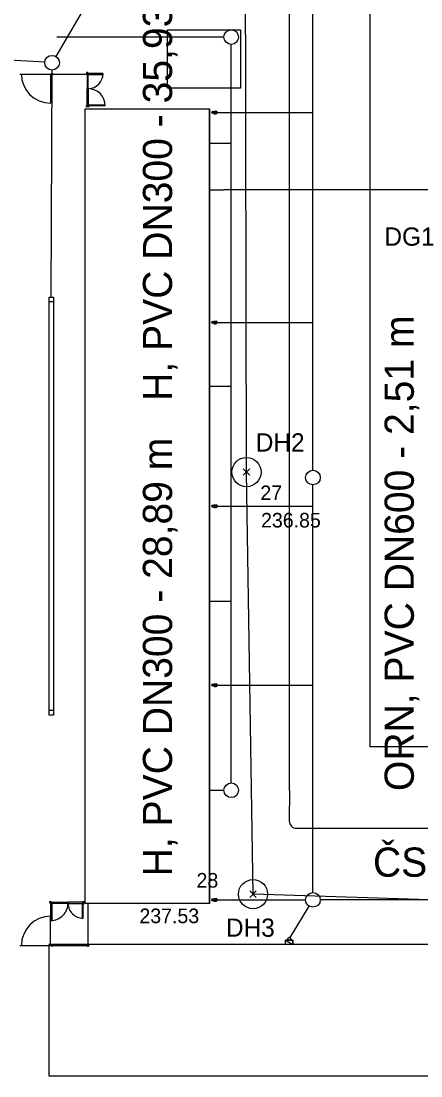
# Model space of a CAD drawing. Extents: x -264234 to -263604, y -1242346 to -1242049.
# Drawn here: x -263972 to -263944.6, y -1242264 to -1242191.8 of the extents above; entities that cross this region are included whole.
import ezdxf

# ---------------------------------------------------------------- set-up
doc = ezdxf.new("R2010")
doc.units = 0
for name, color, linetype in [('KFA_BODY_CISLO', 7, 'Continuous'), ('KFA_BODY_SYMBOL', 7, 'Continuous'), ('KFA_BODY_VYSKA', 7, 'Continuous'), ('KFA_DAZDOVA_KANALIZACIA_retencna_nadrz', 7, 'Continuous'), ('KFA_DAZDOVA_KANALIZACIA_retencna_nadrz_popis', 7, 'Continuous'), ('KFA_DAZDOVA_KANALIZACIA_vetva_G_popis', 7, 'Continuous'), ('KFA_DAZDOVA_KANALIZACIA_vetva_H', 7, 'Continuous'), ('KFA_DAZDOVA_KANALIZACIA_vetva_H_popis', 7, 'Continuous'), ('KFA_JESTV_IS_DSP_-_KANAL_DAZD', 7, 'Continuous'), ('KFA_SITUACIA_DSP', 7, 'Continuous')]:
    doc.layers.add(name, color=color, linetype=linetype)

msp = doc.modelspace()

# ---------------------------------------------------------------- linework, layer by layer
at = {"layer": 'KFA_BODY_SYMBOL'}
for p, q in [((-263956.774, -1242222.873), (-263956.332, -1242222.431)), ((-263956.332, -1242222.873), (-263956.774, -1242222.431)), ((-263956.325, -1242251.762), (-263955.883, -1242251.32)), ((-263955.883, -1242251.762), (-263956.325, -1242251.32))]:
    msp.add_line(p, q, dxfattribs=at)
at = {"layer": 'KFA_DAZDOVA_KANALIZACIA_retencna_nadrz'}
msp.add_lwpolyline([(-263941.017, -1242252.038), (-263942.63, -1242251.985), (-263956.104, -1242251.541)], dxfattribs=at)
at = {"layer": 'KFA_DAZDOVA_KANALIZACIA_vetva_H'}
msp.add_lwpolyline([(-263956.104, -1242251.541), (-263956.553, -1242222.652), (-263956.616, -1242186.719), (-263963.661, -1242184.028)], dxfattribs=at)
for centre in [(-263956.553, -1242222.652), (-263956.104, -1242251.541)]:
    msp.add_circle(centre, 1, dxfattribs=at)
at = {"layer": 'KFA_JESTV_IS_DSP_-_KANAL_DAZD'}
for p, q in [((-263963.914, -1242184.46), (-263969.615, -1242194.201)), ((-263970.367, -1242194.605), (-264044.102, -1242190.483))]:
    msp.add_line(p, q, dxfattribs=at)
msp.add_circle((-263969.868, -1242194.633), 0.5, dxfattribs=at)
at = {"layer": 'KFA_SITUACIA_DSP'}
for p, q in [((-263948.093, -1242087.901), (-263948.093, -1242241.458)), ((-263953.617, -1242244.458), (-263953.617, -1242093.307)), ((-263952, -1242222.527), (-263952, -1242182)), ((-263958.097, -1242192.883), (-263969.542, -1242192.883)), ((-263957.597, -1242243.932), (-263957.597, -1242193.383)), ((-263969.921, -1242210.683), (-263969.869, -1242195.133)), ((-263972.068, -1242195.407), (-263967.418, -1242195.407)), ((-263969.968, -1242195.407), (-263969.968, -1242197.407)), ((-263967.413, -1242195.307), (-263967.513, -1242195.307)), ((-263967.513, -1242195.307), (-263967.513, -1242195.407)), ((-263967.513, -1242195.407), (-263967.413, -1242195.407)), ((-263967.425, -1242195.32), (-263967.5, -1242195.32)), ((-263967.5, -1242195.32), (-263967.5, -1242195.395)), ((-263967.5, -1242195.395), (-263967.425, -1242195.395)), ((-263967.463, -1242195.407), (-263967.463, -1242196.395)), ((-263967.388, -1242195.407), (-263967.463, -1242195.407)), ((-263967.425, -1242195.395), (-263967.425, -1242195.32)), ((-263967.425, -1242195.395), (-263967.425, -1242195.345)), ((-263967.425, -1242195.345), (-263967.325, -1242195.345)), ((-263967.413, -1242195.407), (-263967.413, -1242195.307)), ((-263967.413, -1242195.357), (-263967.363, -1242195.357)), ((-263967.388, -1242196.395), (-263967.388, -1242195.407)), ((-263967.363, -1242195.457), (-263967.388, -1242195.457)), ((-263966.388, -1242195.371), (-263967.375, -1242195.37)), ((-263967.375, -1242195.37), (-263967.375, -1242195.445)), ((-263967.375, -1242195.445), (-263966.388, -1242195.446)), ((-263967.363, -1242195.357), (-263967.363, -1242195.457)), ((-263967.325, -1242195.345), (-263967.325, -1242195.37)), ((-263967.463, -1242197.557), (-263967.463, -1242196.42)), ((-263967.388, -1242196.42), (-263967.388, -1242197.557)), ((-263967.593, -1242252.182), (-263967.593, -1242197.782)), ((-263967.593, -1242197.782), (-263959.093, -1242197.782)), ((-263967.593, -1242197.782), (-263959.097, -1242197.782)), ((-263967.593, -1242252.182), (-263967.593, -1242197.782)), ((-263967.513, -1242197.557), (-263967.413, -1242197.557)), ((-263967.513, -1242197.657), (-263967.513, -1242197.557)), ((-263967.413, -1242197.657), (-263967.513, -1242197.657)), ((-263967.5, -1242197.57), (-263967.425, -1242197.57)), ((-263967.5, -1242197.645), (-263967.5, -1242197.57)), ((-263967.425, -1242197.645), (-263967.5, -1242197.645)), ((-263967.478, -1242197.782), (-263967.358, -1242197.782)), ((-263967.388, -1242197.557), (-263967.463, -1242197.557)), ((-263967.425, -1242197.57), (-263967.425, -1242197.62)), ((-263967.425, -1242197.57), (-263967.425, -1242197.645)), ((-263967.425, -1242197.62), (-263967.325, -1242197.62)), ((-263967.413, -1242197.557), (-263967.413, -1242197.657)), ((-263967.413, -1242197.607), (-263967.363, -1242197.607)), ((-263967.363, -1242197.507), (-263967.388, -1242197.507)), ((-263967.375, -1242197.52), (-263966.238, -1242197.52)), ((-263967.375, -1242197.595), (-263967.375, -1242197.52)), ((-263966.238, -1242197.595), (-263967.375, -1242197.595)), ((-263967.363, -1242197.607), (-263967.363, -1242197.507)), ((-263967.325, -1242197.62), (-263967.325, -1242197.595)), ((-263959.097, -1242197.782), (-263959.093, -1242252.182)), ((-263959.093, -1242197.782), (-263959.093, -1242252.182)), ((-263958.799, -1242197.962), (-263958.762, -1242197.962)), ((-263958.799, -1242198.102), (-263958.762, -1242198.102)), ((-263958.762, -1242197.962), (-263958.742, -1242197.942)), ((-263958.762, -1242198.102), (-263958.742, -1242198.122)), ((-263958.742, -1242197.942), (-263958.637, -1242197.942)), ((-263958.742, -1242198.122), (-263958.637, -1242198.122)), ((-263958.575, -1242198.032), (-263952, -1242198.032)), ((-263959.097, -1242200.132), (-263957.597, -1242200.132)), ((-263959.097, -1242203.332), (-263958.097, -1242203.332)), ((-263924.893, -1242203.332), (-263958.097, -1242203.332)), ((-263970.071, -1242210.684), (-263969.77, -1242210.682)), ((-263970.07, -1242239.282), (-263970.071, -1242210.684)), ((-263970.071, -1242210.983), (-263969.771, -1242210.985)), ((-263969.77, -1242210.682), (-263969.77, -1242239.282)), ((-263958.799, -1242212.337), (-263958.762, -1242212.337)), ((-263958.799, -1242212.477), (-263958.762, -1242212.477)), ((-263958.762, -1242212.337), (-263958.742, -1242212.317)), ((-263958.762, -1242212.477), (-263958.742, -1242212.497)), ((-263958.742, -1242212.317), (-263958.637, -1242212.317)), ((-263958.742, -1242212.497), (-263958.637, -1242212.497)), ((-263958.575, -1242212.407), (-263952, -1242212.407)), ((-263959.097, -1242216.782), (-263957.597, -1242216.782)), ((-263952, -1242251.432), (-263952, -1242223.527)), ((-263958.799, -1242224.912), (-263958.762, -1242224.912)), ((-263958.799, -1242225.052), (-263958.762, -1242225.052)), ((-263958.762, -1242224.912), (-263958.742, -1242224.892)), ((-263958.762, -1242225.052), (-263958.742, -1242225.072)), ((-263958.742, -1242224.892), (-263958.637, -1242224.892)), ((-263958.742, -1242225.072), (-263958.637, -1242225.072)), ((-263958.575, -1242224.982), (-263952, -1242224.982)), ((-263959.097, -1242231.482), (-263957.597, -1242231.482)), ((-263958.799, -1242237.162), (-263958.762, -1242237.162)), ((-263958.799, -1242237.302), (-263958.762, -1242237.302)), ((-263958.762, -1242237.162), (-263958.742, -1242237.142)), ((-263958.762, -1242237.302), (-263958.742, -1242237.322)), ((-263958.742, -1242237.142), (-263958.637, -1242237.142)), ((-263958.742, -1242237.322), (-263958.637, -1242237.322)), ((-263958.575, -1242237.232), (-263952, -1242237.232)), ((-263969.77, -1242238.982), (-263970.07, -1242238.982)), ((-263969.77, -1242239.282), (-263970.07, -1242239.282)), ((-263930.081, -1242241.458), (-263948.093, -1242241.458)), ((-263959.097, -1242244.432), (-263958.097, -1242244.432)), ((-263953.617, -1242244.458), (-263953.619, -1242246.529)), ((-263953.119, -1242247.03), (-263930.082, -1242247.03)), ((-263970.018, -1242252.152), (-263970.018, -1242252.052)), ((-263970.018, -1242252.052), (-263969.918, -1242252.052)), ((-263969.918, -1242252.152), (-263970.018, -1242252.152)), ((-263970.005, -1242252.14), (-263970.005, -1242252.065)), ((-263970.005, -1242252.065), (-263969.93, -1242252.065)), ((-263969.93, -1242252.14), (-263970.005, -1242252.14)), ((-263969.93, -1242252.14), (-263969.98, -1242252.14)), ((-263969.98, -1242252.14), (-263969.98, -1242252.24)), ((-263969.98, -1242252.24), (-263969.955, -1242252.24)), ((-263969.968, -1242252.152), (-263969.968, -1242252.202)), ((-263969.968, -1242252.202), (-263969.868, -1242252.202)), ((-263969.955, -1242253.327), (-263969.955, -1242252.19)), ((-263969.955, -1242252.19), (-263969.88, -1242252.19)), ((-263969.93, -1242252.065), (-263969.93, -1242252.14)), ((-263969.918, -1242252.052), (-263969.918, -1242252.152)), ((-263969.918, -1242252.102), (-263968.78, -1242252.102)), ((-263969.918, -1242252.177), (-263969.918, -1242252.102)), ((-263968.78, -1242252.177), (-263969.918, -1242252.177)), ((-263969.88, -1242252.19), (-263969.88, -1242253.327)), ((-263969.868, -1242252.202), (-263969.868, -1242252.177)), ((-263968.78, -1242252.102), (-263968.78, -1242252.177)), ((-263967.768, -1242252.102), (-263968.755, -1242252.102)), ((-263968.755, -1242252.102), (-263968.755, -1242252.177)), ((-263968.755, -1242252.177), (-263967.768, -1242252.177)), ((-263967.818, -1242252.202), (-263967.818, -1242252.177)), ((-263967.718, -1242252.202), (-263967.818, -1242252.202)), ((-263967.805, -1242252.19), (-263967.807, -1242253.177)), ((-263967.73, -1242252.19), (-263967.805, -1242252.19)), ((-263967.768, -1242252.152), (-263967.768, -1242252.052)), ((-263967.768, -1242252.052), (-263967.668, -1242252.052)), ((-263967.768, -1242252.177), (-263967.768, -1242252.102)), ((-263967.668, -1242252.152), (-263967.768, -1242252.152)), ((-263967.755, -1242252.14), (-263967.755, -1242252.065)), ((-263967.755, -1242252.065), (-263967.68, -1242252.065)), ((-263967.755, -1242252.14), (-263967.705, -1242252.14)), ((-263967.68, -1242252.14), (-263967.755, -1242252.14)), ((-263967.732, -1242253.177), (-263967.73, -1242252.19)), ((-263967.705, -1242252.24), (-263967.73, -1242252.24)), ((-263967.718, -1242252.152), (-263967.718, -1242252.202)), ((-263967.705, -1242252.14), (-263967.705, -1242252.24)), ((-263967.68, -1242252.065), (-263967.68, -1242252.14)), ((-263967.668, -1242252.052), (-263967.668, -1242252.152)), ((-263959.093, -1242252.182), (-263967.593, -1242252.182)), ((-263959.093, -1242252.182), (-263967.593, -1242252.182)), ((-263967.418, -1242252.182), (-263967.418, -1242255.057)), ((-263958.799, -1242251.862), (-263958.762, -1242251.862)), ((-263958.799, -1242252.002), (-263958.762, -1242252.002)), ((-263958.762, -1242251.862), (-263958.742, -1242251.842)), ((-263958.762, -1242252.002), (-263958.742, -1242252.022)), ((-263958.742, -1242251.842), (-263958.637, -1242251.842)), ((-263958.742, -1242252.022), (-263958.637, -1242252.022)), ((-263958.575, -1242251.932), (-263952.5, -1242251.932)), ((-263940.302, -1242251.932), (-263951.5, -1242251.932)), ((-263953.57, -1242254.506), (-263952.26, -1242252.359)), ((-263969.968, -1242255.057), (-263969.968, -1242253.057)), ((-263972.068, -1242255.057), (-263967.418, -1242255.057)), ((-263969.928, -1242255.057), (-263969.808, -1242255.057)), ((-263969.868, -1242255.117), (-263969.868, -1242254.997)), ((-263967.478, -1242255.057), (-263967.358, -1242255.057)), ((-263967.418, -1242255.117), (-263967.418, -1242254.997)), ((-263953.87, -1242254.692), (-263953.37, -1242254.692)), ((-263953.87, -1242254.982), (-263953.87, -1242254.692)), ((-263953.87, -1242254.692), (-263953.37, -1242254.982)), ((-263953.87, -1242254.692), (-263953.37, -1242254.982)), ((-263953.37, -1242254.692), (-263953.87, -1242254.692)), ((-263953.37, -1242254.982), (-263953.87, -1242254.982)), ((-263953.37, -1242254.692), (-263953.37, -1242254.982)), ((-263953.37, -1242254.982), (-263953.37, -1242254.692))]:
    msp.add_line(p, q, dxfattribs=at)
for points in [[(-263961.968, -1242192.382), (-263956.968, -1242192.382), (-263956.968, -1242196.382), (-263961.968, -1242196.382)], [(-263967.597, -1242197.782), (-263959.097, -1242197.782), (-263959.097, -1242252.182), (-263967.597, -1242252.182)]]:
    msp.add_lwpolyline(points, close=True, dxfattribs=at)
msp.add_lwpolyline([(-263929.58, -1242254.982), (-263970.077, -1242254.982), (-263970.077, -1242263.982), (-263929.58, -1242263.982), (-263929.58, -1242254.982)], dxfattribs=at)
for centre, radius in [((-263957.597, -1242192.883), 0.5), ((-263969.868, -1242194.633), 0.5), ((-263969.868, -1242195.407), 0.06), ((-263958.847, -1242198.032), 0.085), ((-263958.847, -1242198.032), 0.0625), ((-263958.637, -1242198.032), 0.0625), ((-263958.847, -1242212.407), 0.085), ((-263958.847, -1242212.407), 0.0625), ((-263958.637, -1242212.407), 0.0625), ((-263952, -1242223.027), 0.5), ((-263958.847, -1242224.982), 0.085), ((-263958.847, -1242224.982), 0.0625), ((-263958.637, -1242224.982), 0.0625), ((-263958.847, -1242237.232), 0.085), ((-263958.847, -1242237.232), 0.0625), ((-263958.637, -1242237.232), 0.0625), ((-263957.597, -1242244.432), 0.5), ((-263952, -1242251.932), 0.5), ((-263958.847, -1242251.932), 0.085), ((-263958.847, -1242251.932), 0.0625), ((-263958.637, -1242251.932), 0.0625), ((-263969.868, -1242255.057), 0.06), ((-263967.418, -1242255.057), 0.06), ((-263953.62, -1242254.592), 0.1)]:
    msp.add_circle(centre, radius, dxfattribs=at)
for centre, radius, start, end in [((-263969.968, -1242195.407), 2, 180, 270), ((-263967.4, -1242195.382), 1.025, 270.60954, 0.60953), ((-263967.4, -1242197.582), 1.175, 359.39047, 89.39046), ((-263958.637, -1242198.032), 0.09, 270, 90), ((-263958.637, -1242212.407), 0.09, 270, 90), ((-263958.637, -1242224.982), 0.09, 270, 90), ((-263958.637, -1242237.232), 0.09, 270, 90), ((-263953.119, -1242246.53), 0.5, 179.95255, 270), ((-263969.943, -1242252.165), 1.175, 269.39046, 359.39047), ((-263967.743, -1242252.165), 1.025, 180.60953, 270.60954), ((-263958.637, -1242251.932), 0.09, 270, 90), ((-263969.968, -1242255.057), 2, 90, 180)]:
    msp.add_arc(centre, radius, start, end, dxfattribs=at)
for centre in [(-263967.4, -1242195.382), (-263967.4, -1242195.382), (-263967.4, -1242197.582), (-263969.943, -1242252.165), (-263969.943, -1242252.165), (-263967.743, -1242252.165)]:
    msp.add_ellipse(centre, major_axis=(0, 0.0125), ratio=0.999995, dxfattribs=at)

# ---------------------------------------------------------------- texts
at = {"layer": 'KFA_BODY_CISLO'}
for s, p in [('27', (-263955.604, -1242224.57)), ('28', (-263959.974, -1242251.095))]:
    msp.add_text(s, height=1, dxfattribs=at).set_placement(p)
at = {"layer": 'KFA_BODY_VYSKA'}
for s, p in [('236.85', (-263955.552, -1242226.446)), ('237.53', (-263963.882, -1242253.529))]:
    msp.add_text(s, height=1, dxfattribs=at).set_placement(p)
at = {"layer": 'KFA_DAZDOVA_KANALIZACIA_retencna_nadrz_popis'}
msp.add_text('ORN, PVC DN600 - 2,51 m', height=2, rotation=90, dxfattribs=at).set_placement((-263945.093, -1242244.485))
msp.add_text('ČS1', height=2, dxfattribs=at).set_placement((-263947.89, -1242250.351))
at = {"layer": 'KFA_DAZDOVA_KANALIZACIA_vetva_G_popis'}
msp.add_text('DG1', height=1.25, dxfattribs=at).set_placement((-263947.106, -1242207.158))
at = {"layer": 'KFA_DAZDOVA_KANALIZACIA_vetva_H_popis'}
for s, p in [('H, PVC DN300 - 35,93 m', (-263961.646, -1242217.779)), ('H, PVC DN300 - 28,89 m', (-263961.646, -1242250.325))]:
    msp.add_text(s, height=2, rotation=90, dxfattribs=at).set_placement(p)
for s, p in [('DH2', (-263955.916, -1242221.249)), ('DH3', (-263957.957, -1242254.459))]:
    msp.add_text(s, height=1.25, dxfattribs=at).set_placement(p)

doc.saveas('drawing.dxf')
